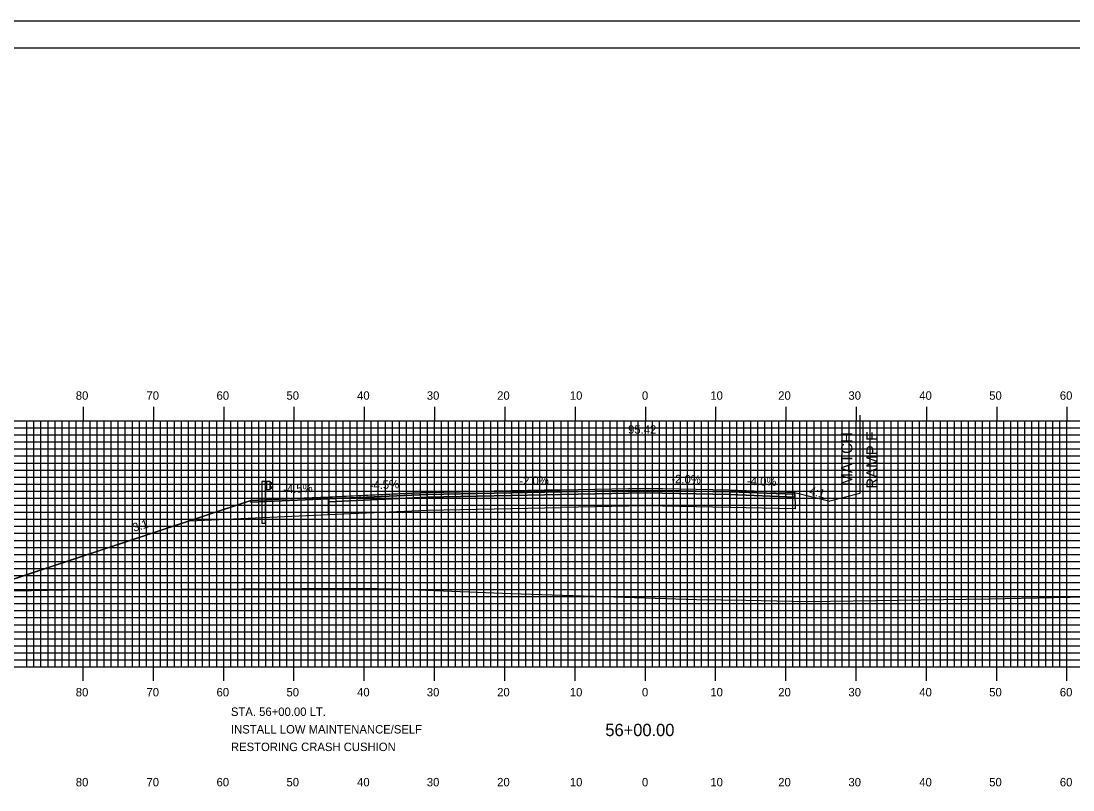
# Model space of a CAD drawing. Extents: x 1756675 to 1757019, y 442591 to 442811.
# Drawn here: x 1756752.2 to 1756901.9, y 442701.2 to 442810.5 of the extents above; entities that cross this region are included whole.
import ezdxf

# ---------------------------------------------------------------- set-up
doc = ezdxf.new("R2010")
doc.units = 0
for name, color, linetype in [('ANNOTATION', 7, 'Continuous'), ('BORDER', 7, 'Continuous'), ('D_Guardrail_Beam_Lt', 7, 'Continuous'), ('D_Roadway_Centerline', 7, 'Continuous'), ('D_Roadway_Centerline_Text', 7, 'Continuous'), ('D_Roadway_Edge_Shoulder', 7, 'Continuous'), ('D_Roadway_Edge_TW', 7, 'Continuous'), ('D_Roadway_Pavement', 7, 'Continuous'), ('D_Roadway_SlopeLines', 7, 'Continuous'), ('D_Roadway_SubGrade', 7, 'Continuous'), ('D_Text_Standard', 7, 'Continuous'), ('H_V ANNOTATION', 7, 'Continuous'), ('MAJOR', 7, 'Continuous'), ('MINOR', 7, 'Continuous'), ('PLOT BOUNDARY', 7, 'Continuous'), ('S_Roadway_Centerline', 7, 'Continuous')]:
    doc.layers.add(name, color=color, linetype=linetype)

msp = doc.modelspace()

# ---------------------------------------------------------------- linework, layer by layer
at = {"layer": 'BORDER'}
msp.add_lwpolyline([(1756691.48, 442596.67), (1757011.48, 442596.67), (1757011.48, 442806.67), (1756691.48, 442806.67)], close=True, dxfattribs=at)
at = {"layer": 'D_Guardrail_Beam_Lt'}
for p, q in [((1756786.51, 442745.06), (1756786.51, 442739.06)), ((1756786.98, 442745.06), (1756786.51, 442745.06)), ((1756787.67, 442745.06), (1756786.98, 442745.06)), ((1756786.98, 442745.06), (1756786.98, 442743.89)), ((1756786.98, 442743.89), (1756787.67, 442743.89)), ((1756787.01, 442739.06), (1756787.01, 442743.89)), ((1756787.05, 442745.06), (1756787.05, 442743.89)), ((1756787.15, 442745.06), (1756787.15, 442743.89)), ((1756787.67, 442743.89), (1756787.67, 442745.06)), ((1756787.67, 442744.97), (1756787.75, 442744.96)), ((1756787.75, 442743.99), (1756787.67, 442743.97)), ((1756787.68, 442744.51), (1756787.68, 442744.44)), ((1756787.91, 442744.71), (1756787.71, 442744.57)), ((1756787.71, 442744.38), (1756787.91, 442744.24)), ((1756787.76, 442744.95), (1756787.91, 442744.85)), ((1756787.91, 442744.1), (1756787.76, 442744)), ((1756787.01, 442739.06), (1756786.51, 442739.06))]:
    msp.add_line(p, q, dxfattribs=at)
for centre, major_axis, start_param, end_param in [((1756787.76, 442744.51), (-0.0789, 0), 5.323254, 6.283185), ((1756787.76, 442744.44), (-0.0789, 0), 6.283185, 7.243116), ((1756787.74, 442744.92), (0.0417, 0), 0.959931, 1.376053), ((1756787.74, 442744.03), (0.0417, 0), 4.907132, 5.323254), ((1756787.86, 442744.78), (0.0877, 0), 5.323254, 7.243116), ((1756787.86, 442744.17), (0.0877, 0), 5.323254, 7.243116)]:
    msp.add_ellipse(centre, major_axis=major_axis, ratio=0.995501, start_param=start_param, end_param=end_param, dxfattribs=at)
at = {"layer": 'D_Roadway_Centerline'}
msp.add_lwpolyline([(1756746.21, 442729.53), (1756746.45, 442729.6), (1756746.5, 442729.61), (1756784.93, 442742.34), (1756786.99, 442742.43), (1756787.74, 442742.47), (1756787.94, 442742.47), (1756792.2, 442742.67), (1756795.97, 442742.83), (1756797.16, 442742.89), (1756798.1, 442742.93), (1756798.44, 442742.94), (1756798.51, 442742.95), (1756803.7, 442743.18), (1756810.03, 442743.46), (1756829.08, 442743.84), (1756841.08, 442744.08), (1756853.08, 442743.84), (1756862.37, 442743.47), (1756867.31, 442742.24)], dxfattribs=at)
at = {"layer": 'D_Roadway_Edge_Shoulder'}
for points in [[(1756853.08, 442743.84), (1756862.37, 442743.47), (1756862.37, 442743.22), (1756853.08, 442743.59)], [(1756795.97, 442742.83), (1756787.94, 442742.47), (1756787.94, 442742.47), (1756784.93, 442742.34), (1756784.93, 442742.09), (1756795.97, 442742.58)]]:
    msp.add_lwpolyline(points, close=True, dxfattribs=at)
at = {"layer": 'D_Roadway_Edge_TW'}
for points in [[(1756829.08, 442743.84), (1756810.03, 442743.46), (1756810.03, 442743.21), (1756829.08, 442743.59)], [(1756829.08, 442743.59), (1756829.08, 442743.84), (1756841.08, 442744.08), (1756853.08, 442743.84), (1756853.08, 442743.59), (1756841.08, 442743.83)], [(1756810.03, 442743.46), (1756795.97, 442742.83), (1756795.97, 442742.58), (1756810.03, 442743.21)]]:
    msp.add_lwpolyline(points, close=True, dxfattribs=at)
msp.add_lwpolyline([(1756810.03, 442743.46), (1756810.03, 442743.21)], dxfattribs=at)
at = {"layer": 'D_Roadway_Pavement'}
for points in [[(1756829.08, 442743.18), (1756829.08, 442743.59), (1756841.08, 442743.83), (1756853.08, 442743.59), (1756853.08, 442743.18), (1756841.08, 442743.42)], [(1756810.03, 442743.21), (1756795.97, 442742.58), (1756795.97, 442742.17), (1756810.03, 442742.8)], [(1756829.08, 442743.59), (1756810.03, 442743.21), (1756810.03, 442742.8), (1756829.08, 442743.18)], [(1756853.08, 442743.59), (1756862.37, 442743.22), (1756862.37, 442742.81), (1756853.08, 442743.18)]]:
    msp.add_lwpolyline(points, close=True, dxfattribs=at)
for points in [[(1756795.97, 442742.58), (1756795.97, 442742.17)], [(1756795.97, 442742.58), (1756795.97, 442742.17)], [(1756810.03, 442743.21), (1756810.03, 442742.8)], [(1756810.03, 442743.21), (1756810.03, 442742.8)]]:
    msp.add_lwpolyline(points, dxfattribs=at)
at = {"layer": 'D_Roadway_SlopeLines'}
msp.add_lwpolyline([(1756784.93, 442742.34), (1756746.21, 442729.53)], dxfattribs=at)
at = {"layer": 'D_Roadway_SubGrade'}
for p, q in [((1756871.58, 442754.46), (1756871.58, 442743.31)), ((1756871.58, 442743.31), (1756867.31, 442742.24))]:
    msp.add_line(p, q, dxfattribs=at)
for points in [[(1756795.97, 442742.17), (1756795.97, 442742.58), (1756784.93, 442742.09), (1756784.93, 442742.34), (1756776.2, 442739.45), (1756795.97, 442740.33)], [(1756810.03, 442742.8), (1756795.97, 442742.17), (1756795.97, 442740.33), (1756810.03, 442740.96)], [(1756829.08, 442743.18), (1756810.03, 442742.8), (1756810.03, 442740.96), (1756829.08, 442741.34)], [(1756829.08, 442741.34), (1756829.08, 442743.18), (1756841.08, 442743.42), (1756853.08, 442743.18), (1756853.08, 442741.34), (1756841.08, 442741.58)], [(1756853.08, 442743.18), (1756862.37, 442742.81), (1756862.37, 442743.22), (1756862.37, 442743.47), (1756862.38, 442741.16), (1756853.08, 442741.34)]]:
    msp.add_lwpolyline(points, close=True, dxfattribs=at)
msp.add_lwpolyline([(1756810.03, 442742.8), (1756810.03, 442740.96)], dxfattribs=at)
at = {"layer": 'MAJOR'}
for p, q in [((1756761.08, 442755.67), (1756761.08, 442753.67)), ((1756771.08, 442755.67), (1756771.08, 442753.67)), ((1756781.08, 442755.67), (1756781.08, 442753.67)), ((1756791.08, 442755.67), (1756791.08, 442753.67)), ((1756801.08, 442755.67), (1756801.08, 442753.67)), ((1756811.08, 442755.67), (1756811.08, 442753.67)), ((1756821.08, 442755.67), (1756821.08, 442753.67)), ((1756831.08, 442755.67), (1756831.08, 442753.67)), ((1756841.08, 442755.67), (1756841.08, 442753.67)), ((1756851.08, 442755.67), (1756851.08, 442753.67)), ((1756861.08, 442755.67), (1756861.08, 442753.67)), ((1756871.08, 442755.67), (1756871.08, 442753.67)), ((1756881.08, 442755.67), (1756881.08, 442753.67)), ((1756891.08, 442755.67), (1756891.08, 442753.67)), ((1756901.08, 442755.67), (1756901.08, 442753.67)), ((1756701.08, 442753.67), (1756981.08, 442753.67)), ((1756701.08, 442753.67), (1756981.08, 442753.67)), ((1756761.08, 442718.67), (1756761.08, 442753.67)), ((1756771.08, 442718.67), (1756771.08, 442753.67)), ((1756781.08, 442718.67), (1756781.08, 442753.67)), ((1756791.08, 442718.67), (1756791.08, 442753.67)), ((1756801.08, 442718.67), (1756801.08, 442753.67)), ((1756811.08, 442718.67), (1756811.08, 442753.67)), ((1756821.08, 442718.67), (1756821.08, 442753.67)), ((1756831.08, 442718.67), (1756831.08, 442753.67)), ((1756841.08, 442718.67), (1756841.08, 442753.67)), ((1756851.08, 442718.67), (1756851.08, 442753.67)), ((1756861.08, 442718.67), (1756861.08, 442753.67)), ((1756871.08, 442718.67), (1756871.08, 442753.67)), ((1756881.08, 442718.67), (1756881.08, 442753.67)), ((1756891.08, 442718.67), (1756891.08, 442753.67)), ((1756901.08, 442718.67), (1756901.08, 442753.67)), ((1756701.08, 442748.67), (1756981.08, 442748.67)), ((1756701.08, 442743.67), (1756981.08, 442743.67)), ((1756701.08, 442738.67), (1756981.08, 442738.67)), ((1756701.08, 442733.67), (1756981.08, 442733.67)), ((1756701.08, 442728.67), (1756981.08, 442728.67)), ((1756701.08, 442723.67), (1756981.08, 442723.67)), ((1756701.08, 442718.67), (1756981.08, 442718.67)), ((1756701.08, 442718.67), (1756981.08, 442718.67)), ((1756761.08, 442716.66), (1756761.08, 442718.67)), ((1756771.08, 442716.66), (1756771.08, 442718.67)), ((1756781.08, 442716.66), (1756781.08, 442718.67)), ((1756791.08, 442716.66), (1756791.08, 442718.67)), ((1756801.08, 442716.66), (1756801.08, 442718.67)), ((1756811.08, 442716.66), (1756811.08, 442718.67)), ((1756821.08, 442716.66), (1756821.08, 442718.67)), ((1756831.08, 442716.66), (1756831.08, 442718.67)), ((1756841.08, 442716.66), (1756841.08, 442718.67)), ((1756851.08, 442716.66), (1756851.08, 442718.67)), ((1756861.08, 442716.66), (1756861.08, 442718.67)), ((1756871.08, 442716.66), (1756871.08, 442718.67)), ((1756881.08, 442716.66), (1756881.08, 442718.67)), ((1756891.08, 442716.66), (1756891.08, 442718.67)), ((1756901.08, 442716.66), (1756901.08, 442718.67))]:
    msp.add_line(p, q, dxfattribs=at)
at = {"layer": 'MINOR'}
for p, q in [((1756753.08, 442718.67), (1756753.08, 442753.67)), ((1756754.08, 442718.67), (1756754.08, 442753.67)), ((1756755.08, 442718.67), (1756755.08, 442753.67)), ((1756756.08, 442718.67), (1756756.08, 442753.67)), ((1756757.08, 442718.67), (1756757.08, 442753.67)), ((1756758.08, 442718.67), (1756758.08, 442753.67)), ((1756759.08, 442718.67), (1756759.08, 442753.67)), ((1756760.08, 442718.67), (1756760.08, 442753.67)), ((1756762.08, 442718.67), (1756762.08, 442753.67)), ((1756763.08, 442718.67), (1756763.08, 442753.67)), ((1756764.08, 442718.67), (1756764.08, 442753.67)), ((1756765.08, 442718.67), (1756765.08, 442753.67)), ((1756766.08, 442718.67), (1756766.08, 442753.67)), ((1756767.08, 442718.67), (1756767.08, 442753.67)), ((1756768.08, 442718.67), (1756768.08, 442753.67)), ((1756769.08, 442718.67), (1756769.08, 442753.67)), ((1756770.08, 442718.67), (1756770.08, 442753.67)), ((1756772.08, 442718.67), (1756772.08, 442753.67)), ((1756773.08, 442718.67), (1756773.08, 442753.67)), ((1756774.08, 442718.67), (1756774.08, 442753.67)), ((1756775.08, 442718.67), (1756775.08, 442753.67)), ((1756776.08, 442718.67), (1756776.08, 442753.67)), ((1756777.08, 442718.67), (1756777.08, 442753.67)), ((1756778.08, 442718.67), (1756778.08, 442753.67)), ((1756779.08, 442718.67), (1756779.08, 442753.67)), ((1756780.08, 442718.67), (1756780.08, 442753.67)), ((1756782.08, 442718.67), (1756782.08, 442753.67)), ((1756783.08, 442718.67), (1756783.08, 442753.67)), ((1756784.08, 442718.67), (1756784.08, 442753.67)), ((1756785.08, 442718.67), (1756785.08, 442753.67)), ((1756786.08, 442718.67), (1756786.08, 442753.67)), ((1756787.08, 442718.67), (1756787.08, 442753.67)), ((1756788.08, 442718.67), (1756788.08, 442753.67)), ((1756789.08, 442718.67), (1756789.08, 442753.67)), ((1756790.08, 442718.67), (1756790.08, 442753.67)), ((1756792.08, 442718.67), (1756792.08, 442753.67)), ((1756793.08, 442718.67), (1756793.08, 442753.67)), ((1756794.08, 442718.67), (1756794.08, 442753.67)), ((1756795.08, 442718.67), (1756795.08, 442753.67)), ((1756796.08, 442718.67), (1756796.08, 442753.67)), ((1756797.08, 442718.67), (1756797.08, 442753.67)), ((1756798.08, 442718.67), (1756798.08, 442753.67)), ((1756799.08, 442718.67), (1756799.08, 442753.67)), ((1756800.08, 442718.67), (1756800.08, 442753.67)), ((1756802.08, 442718.67), (1756802.08, 442753.67)), ((1756803.08, 442718.67), (1756803.08, 442753.67)), ((1756804.08, 442718.67), (1756804.08, 442753.67)), ((1756805.08, 442718.67), (1756805.08, 442753.67)), ((1756806.08, 442718.67), (1756806.08, 442753.67)), ((1756807.08, 442718.67), (1756807.08, 442753.67)), ((1756808.08, 442718.67), (1756808.08, 442753.67)), ((1756809.08, 442718.67), (1756809.08, 442753.67)), ((1756810.08, 442718.67), (1756810.08, 442753.67)), ((1756812.08, 442718.67), (1756812.08, 442753.67)), ((1756813.08, 442718.67), (1756813.08, 442753.67)), ((1756814.08, 442718.67), (1756814.08, 442753.67)), ((1756815.08, 442718.67), (1756815.08, 442753.67)), ((1756816.08, 442718.67), (1756816.08, 442753.67)), ((1756817.08, 442718.67), (1756817.08, 442753.67)), ((1756818.08, 442718.67), (1756818.08, 442753.67)), ((1756819.08, 442718.67), (1756819.08, 442753.67)), ((1756820.08, 442718.67), (1756820.08, 442753.67)), ((1756822.08, 442718.67), (1756822.08, 442753.67)), ((1756823.08, 442718.67), (1756823.08, 442753.67)), ((1756824.08, 442718.67), (1756824.08, 442753.67)), ((1756825.08, 442718.67), (1756825.08, 442753.67)), ((1756826.08, 442718.67), (1756826.08, 442753.67)), ((1756827.08, 442718.67), (1756827.08, 442753.67)), ((1756828.08, 442718.67), (1756828.08, 442753.67)), ((1756829.08, 442718.67), (1756829.08, 442753.67)), ((1756830.08, 442718.67), (1756830.08, 442753.67)), ((1756832.08, 442718.67), (1756832.08, 442753.67)), ((1756833.08, 442718.67), (1756833.08, 442753.67)), ((1756834.08, 442718.67), (1756834.08, 442753.67)), ((1756835.08, 442718.67), (1756835.08, 442753.67)), ((1756836.08, 442718.67), (1756836.08, 442753.67)), ((1756837.08, 442718.67), (1756837.08, 442753.67)), ((1756838.08, 442718.67), (1756838.08, 442753.67)), ((1756839.08, 442718.67), (1756839.08, 442753.67)), ((1756840.08, 442718.67), (1756840.08, 442753.67)), ((1756842.08, 442718.67), (1756842.08, 442753.67)), ((1756843.08, 442718.67), (1756843.08, 442753.67)), ((1756844.08, 442718.67), (1756844.08, 442753.67)), ((1756845.08, 442718.67), (1756845.08, 442753.67)), ((1756846.08, 442718.67), (1756846.08, 442753.67)), ((1756847.08, 442718.67), (1756847.08, 442753.67)), ((1756848.08, 442718.67), (1756848.08, 442753.67)), ((1756849.08, 442718.67), (1756849.08, 442753.67)), ((1756850.08, 442718.67), (1756850.08, 442753.67)), ((1756852.08, 442718.67), (1756852.08, 442753.67)), ((1756853.08, 442718.67), (1756853.08, 442753.67)), ((1756854.08, 442718.67), (1756854.08, 442753.67)), ((1756855.08, 442718.67), (1756855.08, 442753.67)), ((1756856.08, 442718.67), (1756856.08, 442753.67)), ((1756857.08, 442718.67), (1756857.08, 442753.67)), ((1756858.08, 442718.67), (1756858.08, 442753.67)), ((1756859.08, 442718.67), (1756859.08, 442753.67)), ((1756860.08, 442718.67), (1756860.08, 442753.67)), ((1756862.08, 442718.67), (1756862.08, 442753.67)), ((1756863.08, 442718.67), (1756863.08, 442753.67)), ((1756864.08, 442718.67), (1756864.08, 442753.67)), ((1756865.08, 442718.67), (1756865.08, 442753.67)), ((1756866.08, 442718.67), (1756866.08, 442753.67)), ((1756867.08, 442718.67), (1756867.08, 442753.67)), ((1756868.08, 442718.67), (1756868.08, 442753.67)), ((1756869.08, 442718.67), (1756869.08, 442753.67)), ((1756870.08, 442718.67), (1756870.08, 442753.67)), ((1756872.08, 442718.67), (1756872.08, 442753.67)), ((1756873.08, 442718.67), (1756873.08, 442753.67)), ((1756874.08, 442718.67), (1756874.08, 442753.67)), ((1756875.08, 442718.67), (1756875.08, 442753.67)), ((1756876.08, 442718.67), (1756876.08, 442753.67)), ((1756877.08, 442718.67), (1756877.08, 442753.67)), ((1756878.08, 442718.67), (1756878.08, 442753.67)), ((1756879.08, 442718.67), (1756879.08, 442753.67)), ((1756880.08, 442718.67), (1756880.08, 442753.67)), ((1756882.08, 442718.67), (1756882.08, 442753.67)), ((1756883.08, 442718.67), (1756883.08, 442753.67)), ((1756884.08, 442718.67), (1756884.08, 442753.67)), ((1756885.08, 442718.67), (1756885.08, 442753.67)), ((1756886.08, 442718.67), (1756886.08, 442753.67)), ((1756887.08, 442718.67), (1756887.08, 442753.67)), ((1756888.08, 442718.67), (1756888.08, 442753.67)), ((1756889.08, 442718.67), (1756889.08, 442753.67)), ((1756890.08, 442718.67), (1756890.08, 442753.67)), ((1756892.08, 442718.67), (1756892.08, 442753.67)), ((1756893.08, 442718.67), (1756893.08, 442753.67)), ((1756894.08, 442718.67), (1756894.08, 442753.67)), ((1756895.08, 442718.67), (1756895.08, 442753.67)), ((1756896.08, 442718.67), (1756896.08, 442753.67)), ((1756897.08, 442718.67), (1756897.08, 442753.67)), ((1756898.08, 442718.67), (1756898.08, 442753.67)), ((1756899.08, 442718.67), (1756899.08, 442753.67)), ((1756900.08, 442718.67), (1756900.08, 442753.67)), ((1756701.08, 442752.67), (1756981.08, 442752.67)), ((1756701.08, 442751.67), (1756981.08, 442751.67)), ((1756701.08, 442750.67), (1756981.08, 442750.67)), ((1756701.08, 442749.67), (1756981.08, 442749.67)), ((1756701.08, 442747.67), (1756981.08, 442747.67)), ((1756701.08, 442746.67), (1756981.08, 442746.67)), ((1756701.08, 442745.67), (1756981.08, 442745.67)), ((1756701.08, 442744.67), (1756981.08, 442744.67)), ((1756701.08, 442742.67), (1756981.08, 442742.67)), ((1756701.08, 442741.67), (1756981.08, 442741.67)), ((1756701.08, 442740.67), (1756981.08, 442740.67)), ((1756701.08, 442739.67), (1756981.08, 442739.67)), ((1756701.08, 442737.67), (1756981.08, 442737.67)), ((1756701.08, 442736.67), (1756981.08, 442736.67)), ((1756701.08, 442735.67), (1756981.08, 442735.67)), ((1756701.08, 442734.67), (1756981.08, 442734.67)), ((1756701.08, 442732.67), (1756981.08, 442732.67)), ((1756701.08, 442731.67), (1756981.08, 442731.67)), ((1756701.08, 442730.67), (1756981.08, 442730.67)), ((1756701.08, 442729.67), (1756981.08, 442729.67)), ((1756701.08, 442727.67), (1756981.08, 442727.67)), ((1756701.08, 442726.67), (1756981.08, 442726.67)), ((1756701.08, 442725.67), (1756981.08, 442725.67)), ((1756701.08, 442724.67), (1756981.08, 442724.67)), ((1756701.08, 442722.67), (1756981.08, 442722.67)), ((1756701.08, 442721.67), (1756981.08, 442721.67)), ((1756701.08, 442720.67), (1756981.08, 442720.67)), ((1756701.08, 442719.67), (1756981.08, 442719.67))]:
    msp.add_line(p, q, dxfattribs=at)
at = {"layer": 'PLOT BOUNDARY'}
msp.add_lwpolyline([(1756675.3, 442590.55), (1757015.3, 442590.55), (1757015.3, 442810.55), (1756675.3, 442810.55)], close=True, dxfattribs=at)
at = {"layer": 'S_Roadway_Centerline'}
msp.add_lwpolyline([(1756701.08, 442729.47), (1756728.63, 442729.61), (1756749.63, 442729.51), (1756753.73, 442729.53), (1756758.51, 442729.63), (1756775.1, 442729.71), (1756800.77, 442729.86), (1756805.16, 442729.75), (1756821.92, 442729.09), (1756848.37, 442728.26), (1756855.36, 442728.14), (1756864.2, 442727.97), (1756889.97, 442728.34), (1756908.46, 442728.73), (1756912.95, 442728.86), (1756917.38, 442728.94), (1756917.49, 442728.92), (1756956.52, 442729.49), (1756976.5, 442729.7), (1756981.08, 442729.72)], dxfattribs=at)

# ---------------------------------------------------------------- texts
at = {"layer": 'ANNOTATION'}
for s, height, rotation, p in [('MATCH', 1.6, 90, (1756870.54, 442744.45)), ('RAMP E', 1.6, 90, (1756874.14, 442744.02)), ('-2.0%', 1.2, 1.1458, (1756823.16, 442744.53)), ('-2.0%', 1.2, 358.8542, (1756844.77, 442744.81)), ('-4.0%', 1.2, 357.7094, (1756855.52, 442744.55)), ('-4.5%', 1.2, 2.5612, (1756789.56, 442743.35)), ('-4.5%', 1.2, 2.5616, (1756801.87, 442743.9)), ('4:1', 1.2, 345.9518, (1756864.3, 442743.2)), ('3:1', 1.2, 16.8729, (1756768.31, 442737.88))]:
    msp.add_text(s, height=height, rotation=rotation, dxfattribs=at).set_placement(p)
at = {"layer": 'D_Roadway_Centerline'}
for s in ['C', 'L']:
    msp.add_text(s, height=0.0146, dxfattribs=at).set_placement((1756841.08, 442744.08))
at = {"layer": 'D_Roadway_Centerline_Text'}
msp.add_text('95.42', height=1.2, dxfattribs=at).set_placement((1756838.62, 442751.84))
at = {"layer": 'D_Text_Standard'}
for s, p in [('STA. 56+00.00 LT.', (1756782.11, 442711.69)), ('INSTALL LOW MAINTENANCE/SELF', (1756782.11, 442709.19)), ('RESTORING CRASH CUSHION', (1756782.11, 442706.69))]:
    msp.add_text(s, height=1.2, dxfattribs=at).set_placement(p)
at = {"layer": 'H_V ANNOTATION'}
for s, height, p in [('80', 1.2, (1756760.03, 442756.67)), ('70', 1.2, (1756770.09, 442756.67)), ('60', 1.2, (1756780.06, 442756.67)), ('50', 1.2, (1756790.01, 442756.67)), ('40', 1.2, (1756800.06, 442756.67)), ('30', 1.2, (1756809.98, 442756.67)), ('20', 1.2, (1756819.99, 442756.67)), ('10', 1.2, (1756830.33, 442756.67)), ('0', 1.2, (1756840.6, 442756.67)), ('10', 1.2, (1756850.33, 442756.67)), ('20', 1.2, (1756859.99, 442756.67)), ('30', 1.2, (1756869.98, 442756.67)), ('40', 1.2, (1756880.06, 442756.67)), ('50', 1.2, (1756890.01, 442756.67)), ('60', 1.2, (1756900.06, 442756.67)), ('80', 1.2, (1756760.03, 442714.47)), ('70', 1.2, (1756770.09, 442714.47)), ('60', 1.2, (1756780.06, 442714.47)), ('50', 1.2, (1756790.01, 442714.47)), ('40', 1.2, (1756800.06, 442714.47)), ('30', 1.2, (1756809.98, 442714.47)), ('20', 1.2, (1756819.99, 442714.47)), ('10', 1.2, (1756830.33, 442714.47)), ('0', 1.2, (1756840.6, 442714.47)), ('10', 1.2, (1756850.33, 442714.47)), ('20', 1.2, (1756859.99, 442714.47)), ('30', 1.2, (1756869.98, 442714.47)), ('40', 1.2, (1756880.06, 442714.47)), ('50', 1.2, (1756890.01, 442714.47)), ('60', 1.2, (1756900.06, 442714.47)), ('56+00.00', 1.75, (1756835.39, 442708.82)), ('80', 1.2, (1756760.03, 442701.67)), ('70', 1.2, (1756770.09, 442701.67)), ('60', 1.2, (1756780.06, 442701.67)), ('50', 1.2, (1756790.01, 442701.67)), ('40', 1.2, (1756800.06, 442701.67)), ('30', 1.2, (1756809.98, 442701.67)), ('20', 1.2, (1756819.99, 442701.67)), ('10', 1.2, (1756830.33, 442701.67)), ('0', 1.2, (1756840.6, 442701.67)), ('10', 1.2, (1756850.33, 442701.67)), ('20', 1.2, (1756859.99, 442701.67)), ('30', 1.2, (1756869.98, 442701.67)), ('40', 1.2, (1756880.06, 442701.67)), ('50', 1.2, (1756890.01, 442701.67)), ('60', 1.2, (1756900.06, 442701.67))]:
    msp.add_text(s, height=height, dxfattribs=at).set_placement(p)

doc.saveas('drawing.dxf')
